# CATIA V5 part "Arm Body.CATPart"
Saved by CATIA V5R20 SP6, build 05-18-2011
Part number: Arm Body
Bounding box of the stored display mesh (mm): x 0 to 16, y -5.5 to 5.5, z 0 to 26
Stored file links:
  E:\#01 CATIA Lecture Materials\#06 DMU\#03 DMU Page01 KIN EX03\Arm Body.CATPart
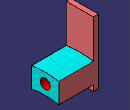
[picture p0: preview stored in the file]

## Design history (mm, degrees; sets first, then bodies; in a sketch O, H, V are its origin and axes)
Set1 "Reference Data"
  Point1 "Center Point": (0, 0, 0)
Body1 (main body)
  Body2
    Sketch1 on yz-plane, origin (0, 0, 0), H (0, 1, 0), V (0, 0, 1)
      point P1 (-5.5, 0)
      line L1 (-5.5, 0) -> (5.5, 0)
      line L2 (5.5, 0) -> (5.5, 26)
      line L3 (5.5, 26) -> (-5.5, 26)
      line L4 (-5.5, 26) -> (-5.5, 0)
      distance L4 L2 = 11
      distance L3 H = 26
      coincidence: P1 H
      horizontal: L1 H, L3 H
      vertical: L2 V, L4 V
      symmetry: L4 L2 V
    Pad1: profile Sketch1, direction (1, 0, 0), length 2
  Assemble1: tool Body2
  Body3
    Sketch2 on yz-plane, origin (0, 0, 0), H (0, 1, 0), V (0, 0, 1)
      construction arc A1 centre (0, -23) radius 30 from (5.5, 6.4915) to (-5.5, 6.4915) ccw
      point P1 (0, -23)
      point P2 (5.5, 6.4915)
      point P3 (-5.5, 6.4915)
      arc A2 centre (0, -23) radius 34 from (5.5, 10.5522) to (-5.5, 10.5522) ccw
      point P4 (6.2333, 10.4237)
      point P5 (-6.2333, 10.4237)
      construction line L1 (5.5, 6.4915) -> (6.2333, 10.4237)
      construction line L2 (-5.5, 6.4915) -> (-6.2333, 10.4237)
      arc A3 centre (0, -23) radius 26 from (5.5, 2.4116) to (-5.5, 2.4116) ccw
      point P6 (4.7667, 2.5593)
      point P7 (-4.7667, 2.5593)
      construction line L3 (5.5, 6.4915) -> (4.7667, 2.5593)
      construction line L4 (-5.5, 6.4915) -> (-4.7667, 2.5593)
      projected line E1 (-5.5, 26) -> (-5.5, 0) from edge [face of Pad1 from Sketch1.L4 | end face of Pad1]
      projected line E2 (-5.5, 10.5522) -> (-5.5, 2.4116) from edge [face of Pad1 from Sketch1.L4 | end face of Pad1]
      projected line E3 (5.5, 0) -> (5.5, 26) from edge [face of Pad1 from Sketch1.L2 | end face of Pad1]
      projected line E4 (5.5, 2.4116) -> (5.5, 10.5522) from edge [face of Pad1 from Sketch1.L2 | end face of Pad1]
      radius A1 = 30
      distance H A1 = 7
      distance A1 A2 = 4
      distance A1 A3 = 4
      coincidence: P1 V, L1 P1, L2 P1, L3 P1, L4 P1, P5 A2, P4 A2, P6 A3, P7 A3, P3 E1, P2 E3
      concentricity: A1 A2, A1 A3
    Pad2: profile Sketch2, direction (1, 0, 0), length 16
  Assemble2: tool Body3
  Body4 "Hole Body(M4)"
    Sketch3 on yz-plane, origin (0, 0, 0), H (0, 1, 0), V (0, 0, 1)
      construction circle A1 centre (0, -23) radius 30
      point P1 (0, -23)
      circle A2 centre (0, 7) radius 2
      point P2 (0, 7)
      radius A1 = 30
      distance P1 H = 23
      radius A2 = 2
      coincidence: P1 V, P2 A1, P2 V
    Pad3: profile Sketch3, direction (1, 0, 0), length 20
  Remove1: tool Body4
